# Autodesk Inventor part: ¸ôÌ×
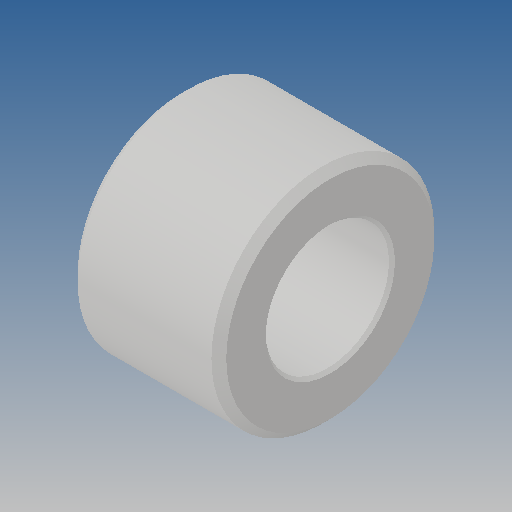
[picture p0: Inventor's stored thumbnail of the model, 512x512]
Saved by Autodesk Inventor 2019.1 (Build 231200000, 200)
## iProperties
Created: 2012-10
Part Number: ¸ôÌ×
Material: Ogólny
Document SubType Name: Modeling
Designer: CADENGINEERING4
Density: 1 g/cm^3
Appearance: Domyślna
Author: CADENGINEERING4
Revision Number: ÈÎºÎ
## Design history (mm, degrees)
feature "Ðý×ª1"
node "Bryła1"
